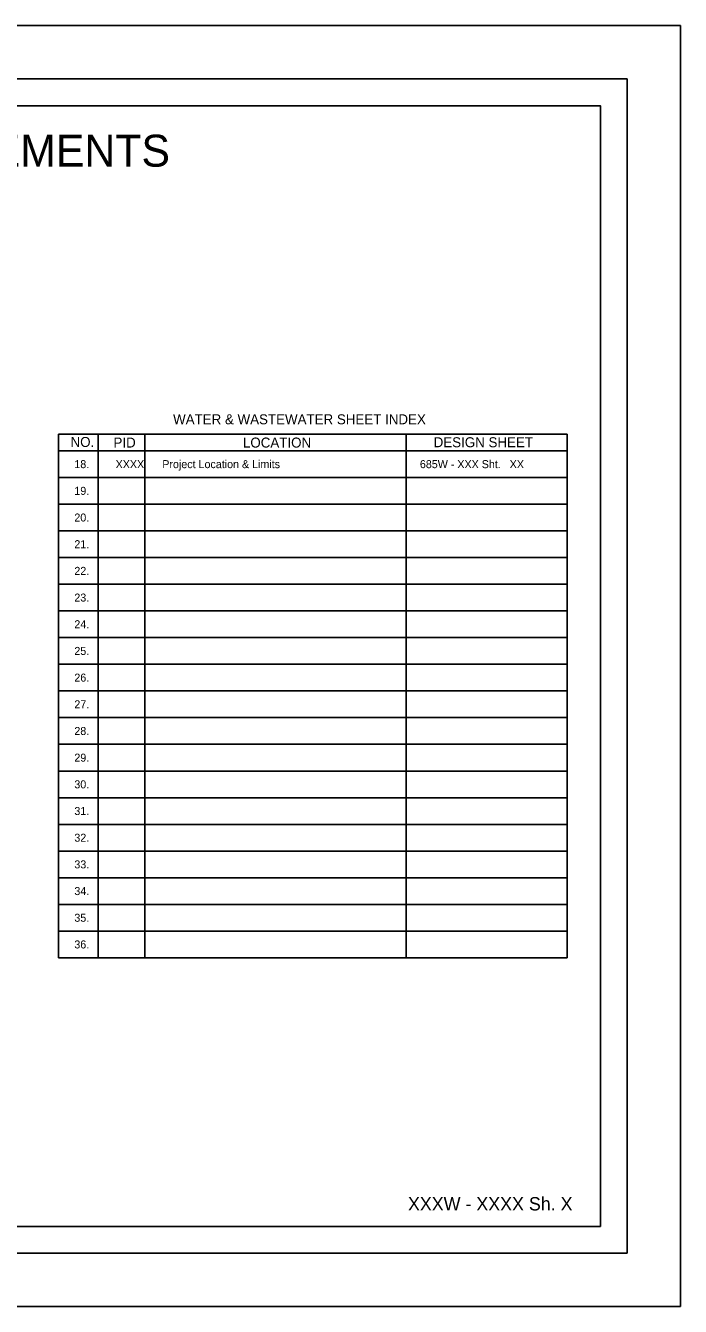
# Model space of a CAD drawing. Extents: x 105094 to 105814, y -291615 to -291123.
# Drawn here: x 105568.6 to 105814.1, y -291608.4 to -291128.4 of the extents above; entities that cross this region are included whole.
import ezdxf

# ---------------------------------------------------------------- set-up
doc = ezdxf.new("R2010")
doc.units = 0
doc.layers.add('G_BORDER', color=7, linetype='Continuous')
doc.layers.add('G_SHEET_EDGE', color=7, linetype='Continuous')

msp = doc.modelspace()

# ---------------------------------------------------------------- linework, layer by layer
at = {"layer": 'G_BORDER'}
for p, q in [((105580.92, -291281.56), (105771.71, -291281.56)), ((105580.92, -291281.56), (105580.92, -291477.75)), ((105595.86, -291281.56), (105595.86, -291477.75)), ((105613.33, -291281.56), (105613.33, -291477.75)), ((105711.37, -291281.56), (105711.37, -291477.75)), ((105771.71, -291281.56), (105771.71, -291477.75)), ((105580.92, -291287.75), (105771.71, -291287.75)), ((105580.92, -291287.75), (105771.71, -291287.75)), ((105580.92, -291297.75), (105771.71, -291297.75)), ((105580.92, -291307.75), (105771.71, -291307.75)), ((105580.92, -291317.75), (105771.71, -291317.75)), ((105580.92, -291327.75), (105771.71, -291327.75)), ((105580.92, -291337.75), (105771.71, -291337.75)), ((105580.92, -291347.75), (105771.71, -291347.75)), ((105580.92, -291357.75), (105771.71, -291357.75)), ((105580.92, -291367.75), (105771.71, -291367.75)), ((105580.92, -291377.75), (105771.71, -291377.75)), ((105580.92, -291387.75), (105771.71, -291387.75)), ((105580.92, -291397.75), (105771.71, -291397.75)), ((105580.92, -291407.75), (105771.71, -291407.75)), ((105580.92, -291417.75), (105771.71, -291417.75)), ((105580.92, -291427.75), (105771.71, -291427.75)), ((105580.92, -291437.75), (105771.71, -291437.75)), ((105580.92, -291447.75), (105771.71, -291447.75)), ((105580.92, -291457.75), (105771.71, -291457.75)), ((105580.92, -291467.75), (105771.71, -291467.75)), ((105580.92, -291477.75), (105771.71, -291477.75)), ((105580.92, -291477.75), (105771.71, -291477.75))]:
    msp.add_line(p, q, dxfattribs=at)
msp.add_lwpolyline([(105134.14, -291158.4), (105784.14, -291158.4), (105784.14, -291578.4), (105134.14, -291578.4)], close=True, dxfattribs=at)
at = {"layer": 'G_SHEET_EDGE'}
for points in [[(105094.14, -291608.4), (105814.14, -291608.4), (105814.14, -291128.4), (105094.14, -291128.4)], [(105114.14, -291148.4), (105794.14, -291148.4), (105794.14, -291588.4), (105114.14, -291588.4)]]:
    msp.add_lwpolyline(points, close=True, dxfattribs=at)

# ---------------------------------------------------------------- texts
at = {"layer": 'G_BORDER'}
for s, height, p in [('WATER AND WASTEWATER MAIN REPLACEMENTS', 12, (105226.93, -291181.27)), ('WATER & WASTEWATER SHEET INDEX', 3.7405, (105623.94, -291277.81)), ('NO.', 3.741, (105585.49, -291286.31)), ('PID', 3.741, (105601.59, -291286.53)), ('LOCATION', 3.741, (105650.13, -291286.53)), ('DESIGN SHEET', 3.7405, (105721.63, -291286.41)), ('18.', 3, (105586.92, -291294.25)), ('XXXX', 3, (105602.4, -291294.25)), ('Project Location & Limits', 3, (105619.89, -291294.25)), ('685W - XXX Sht.   XX', 3, (105716.47, -291294.25)), ('19.', 3, (105586.92, -291304.25)), ('20.', 3, (105586.92, -291314.25)), ('21.', 3, (105586.92, -291324.25)), ('22.', 3, (105586.92, -291334.25)), ('23.', 3, (105586.92, -291344.25)), ('24.', 3, (105586.92, -291354.25)), ('25.', 3, (105586.92, -291364.25)), ('26.', 3, (105586.92, -291374.25)), ('27.', 3, (105586.92, -291384.25)), ('28.', 3, (105586.92, -291394.25)), ('29.', 3, (105586.92, -291404.25)), ('30.', 3, (105586.92, -291414.25)), ('31.', 3, (105586.92, -291424.25)), ('32.', 3, (105586.92, -291434.25)), ('33.', 3, (105586.92, -291444.25)), ('34.', 3, (105586.92, -291454.25)), ('35.', 3, (105586.92, -291464.25)), ('36.', 3, (105586.92, -291474.25)), ('XXXW - XXXX Sh. X', 5, (105712.01, -291572.45))]:
    msp.add_text(s, height=height, dxfattribs=at).set_placement(p)

doc.saveas('drawing.dxf')
